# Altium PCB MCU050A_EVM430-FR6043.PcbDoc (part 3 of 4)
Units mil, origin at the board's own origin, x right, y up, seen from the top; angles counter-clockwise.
Board outline 6000 x 4000 mil, 4 copper layers (Top Layer, GND, PWR, Bottom Layer), stack 61.2 mil thick; 337 components, 255 nets, 1099 pads, 437 vias.
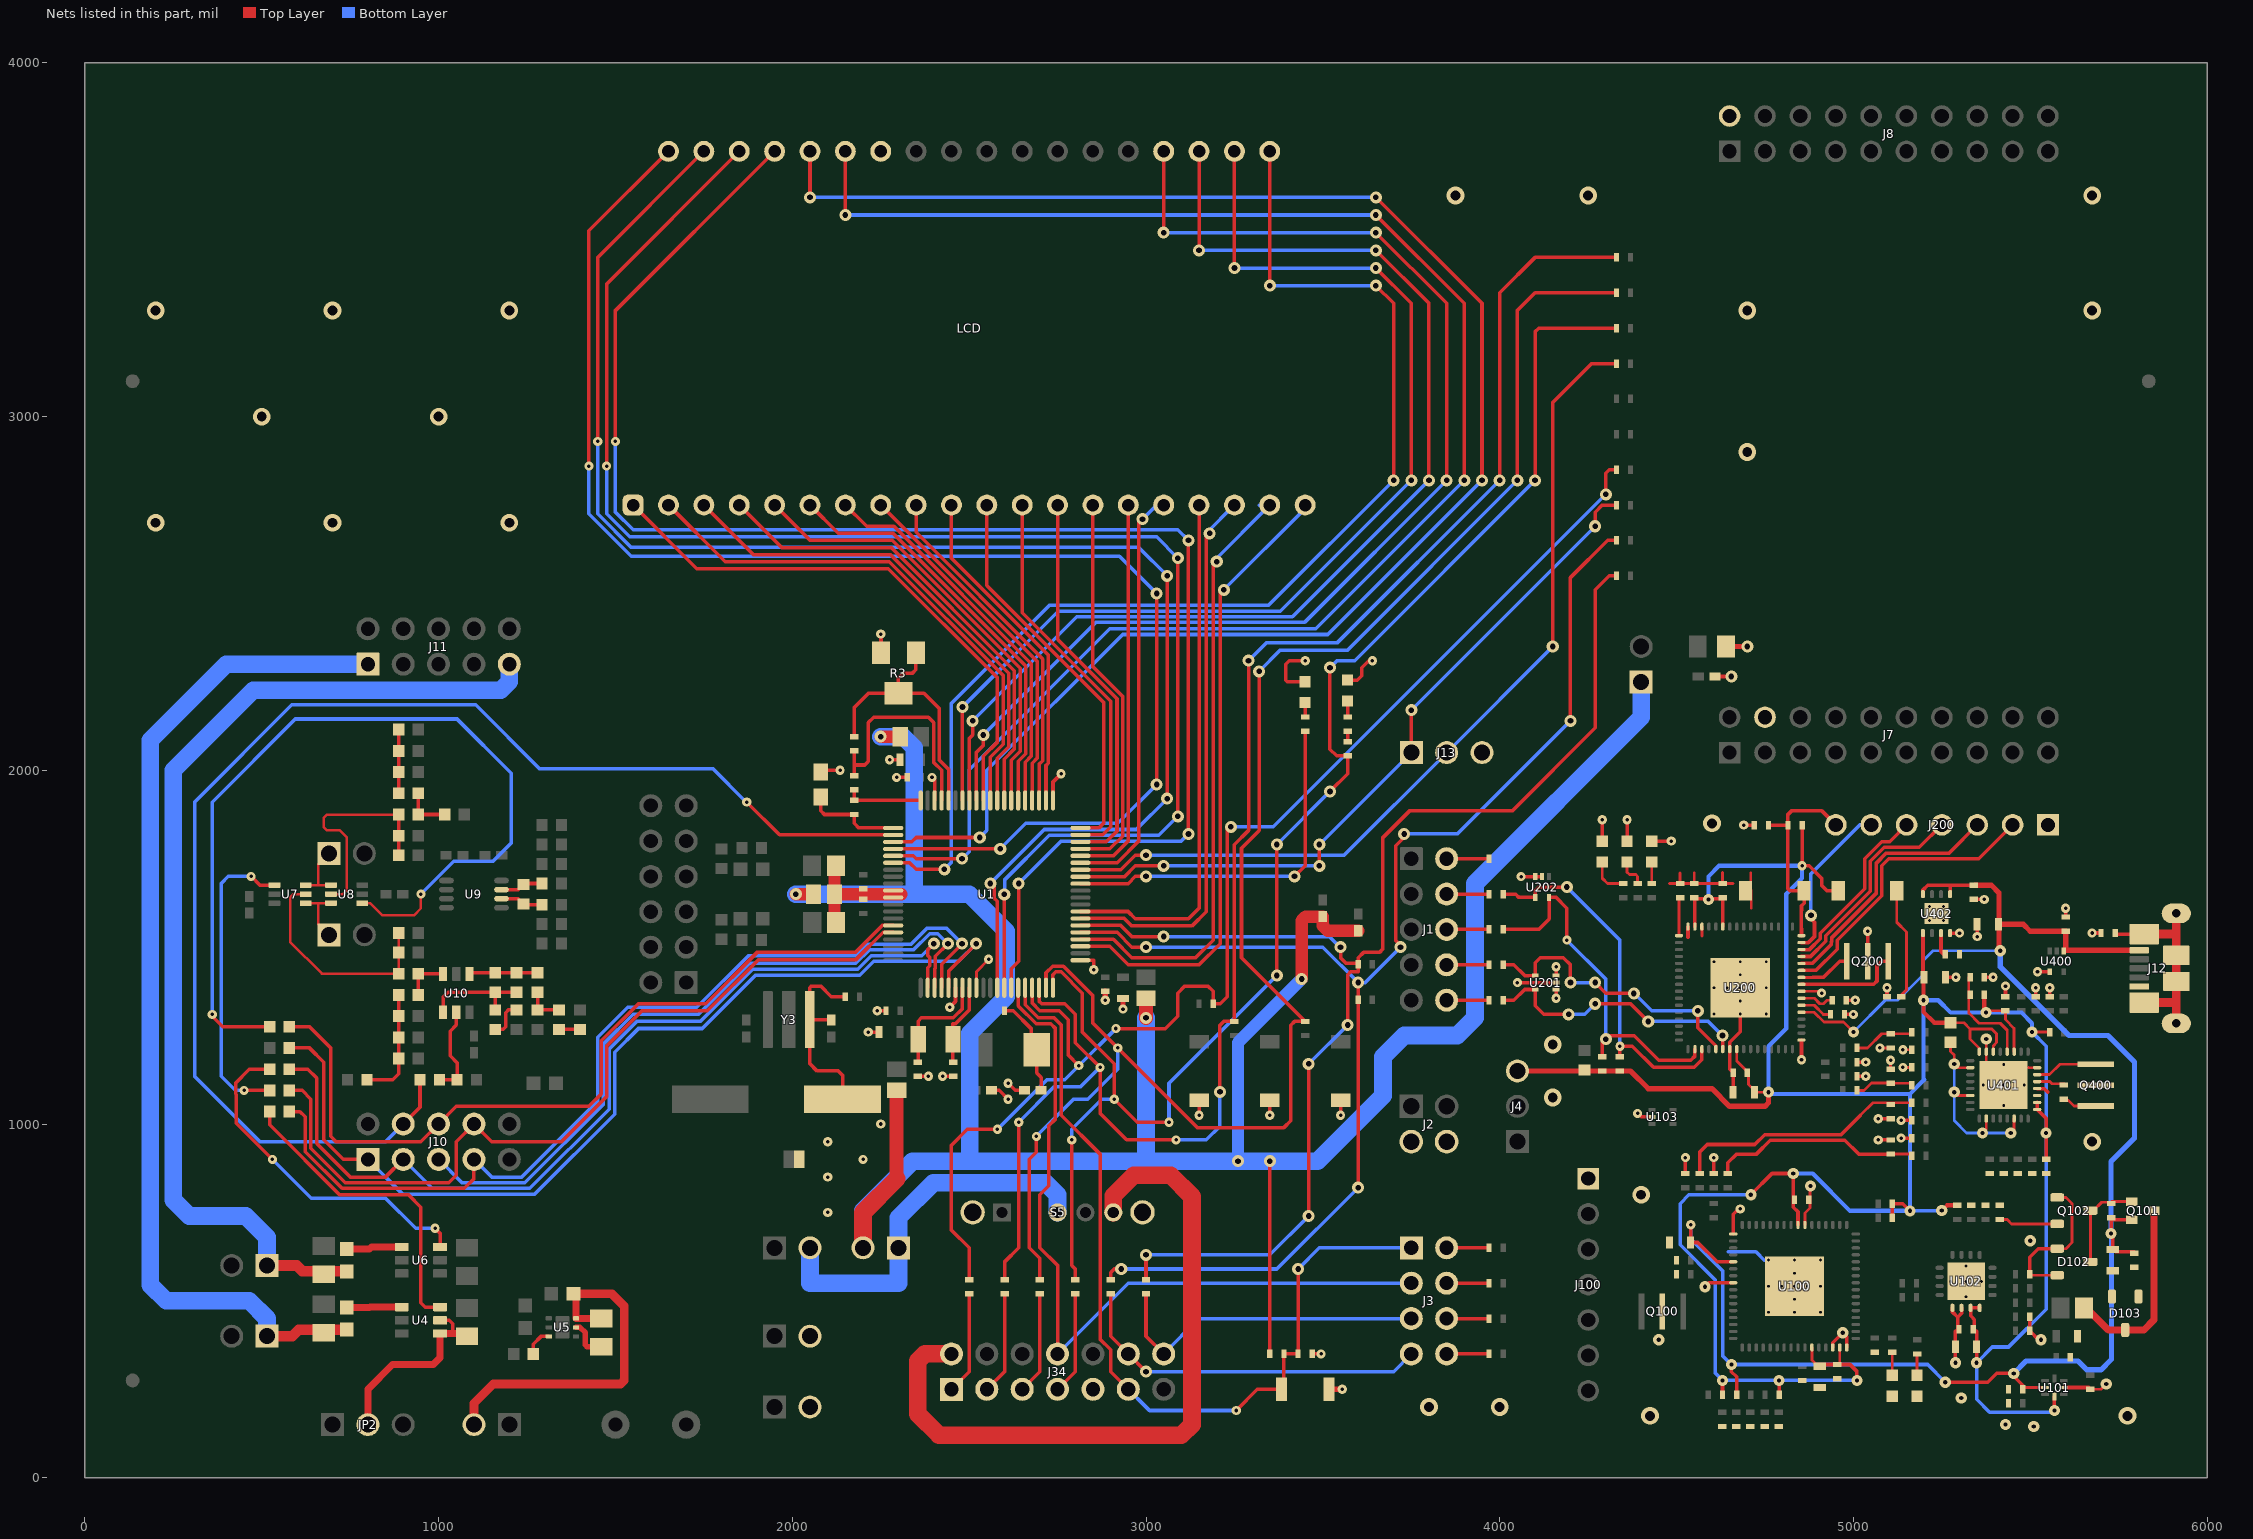
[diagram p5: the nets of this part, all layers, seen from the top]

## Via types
v1: diameter 26, hole 10, Top Layer to Bottom Layer, tented both sides, 173 vias
v2: diameter 34, hole 16, Top Layer to Bottom Layer, tented both sides, 142 vias
v3: diameter 31.5, hole 11.81, Top Layer to Bottom Layer, tented both sides, 56 vias
v4: diameter 19.68, hole 7.87, Top Layer to Bottom Layer, tented both sides, 35 vias
v5: diameter 50, hole 28, Top Layer to Bottom Layer, tented both sides, 23 vias
v6: diameter 19.68, hole 7.87, Top Layer to Bottom Layer, 7 vias
v7: diameter 34, hole 16, Top Layer to Bottom Layer, 1 vias

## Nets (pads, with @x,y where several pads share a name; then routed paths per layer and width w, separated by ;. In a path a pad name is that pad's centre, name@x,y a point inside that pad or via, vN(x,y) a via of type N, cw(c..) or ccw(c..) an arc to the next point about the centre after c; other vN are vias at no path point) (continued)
HID-BRIDGE_RST: C210.1 J200.7 R209.1 S201.2 U200.64 | length 599.8
  Top Layer w10: C210.1@4760,1845 R209.1@4815,1845 ; U200.64@4853.23,1532.68 4853.23,1551.65 4852,1552.88 4852,1602.83 4853.23,1604.05 4853.23,1617.06 4860.63,1624.46 S201.2@4860.63,1660 4820,1660 4815,1665 R209.1@4815,1845 ; J200.7@4950.31,1845.79 4911.1,1885 4825,1885 4815,1875 R209.1@4815,1845
HID-BRIDGE_RXD: R216.1 U200.38 U201.5 | length 776.8
  Top Layer w10: R216.1@4010,1350 4040.08,1350 4070.39,1380.31 U201.5@4100.47,1380.31 4100.47,1334.53 4125,1310 v2(4195,1310) ; v2(4270,1340) 4370,1340 v2(4420,1290) ; v2(4630,1250) 4630.79,1249.21 U200.38@4630.79,1211.77
  Bottom Layer w10: v2(4195,1310) 4240,1310 v2(4270,1340) ; v2(4420,1290) 4590,1290 v2(4630,1250)
HID-BRIDGE_SCL: R200.1 R213.1 U200.35 U202.4 | length 1045.6
  Top Layer w10: R213.1@4010,1650 4045,1650 4054.53,1640.47 U202.4@4100.31,1640.47 4100.31,1660.32 4110,1670 v2(4190,1670) ; R200.1@4340,1190 v1(4340,1220) 4375,1220 4435,1160 4550,1160 4571.73,1181.73 U200.35@4571.73,1211.77
  Bottom Layer w10: v2(4190,1670) 4340,1520 v1(4340,1220)
HID-BRIDGE_SDA: R208.1 R214.1 U200.34 U202.5 | length 1051.2
  Top Layer w10: R214.1@4010,1550 4110,1550 4139.69,1579.69 U202.5@4139.69,1640.47 4159.53,1640.47 4190,1610 v1(4190,1520) ; R208.1@4290,1190 4290,1230 v2(4300,1240) 4300,1250 4380,1250 4450,1180 4540,1180 4552.05,1192.05 U200.34@4552.05,1211.77
  Bottom Layer w10: v1(4190,1520) 4300,1410 v2(4300,1240)
HID-BRIDGE_TCK: J200.6 U200.63 | length 452.9
  Top Layer w10: U200.63@4853.23,1512.99 4872.98,1512.99 4890,1530 4890,1570 4880,1580 v2(4880,1590)
  Bottom Layer w10: v2(4880,1590) 4880,1707.17 5018.61,1845.79 J200.6@5050.31,1845.79
HID-BRIDGE_TDI: J200.4 U200.61 | length 610.1
  Top Layer w10: U200.61@4853.23,1473.61 4878.86,1473.61 4922,1516.75 4922,1532.25 5048,1658.25 5048,1743.25 5086.75,1782 5186.53,1782 J200.4@5250.31,1845.79
HID-BRIDGE_TDO: J200.3 U200.60 | length 719.5
  Top Layer w10: U200.60@4853.23,1453.91 4883.91,1453.91 4938,1508 4938,1515 4938.2,1515.2 4938.2,1525.82 5064,1651.63 5064,1736.63 5093.37,1766 5270.53,1766 J200.3@5350.31,1845.79
HID-BRIDGE_TEST: J200.2 U200.59 | length 832
  Top Layer w10: U200.59@4853.23,1434.22 4894.23,1434.22 4954.2,1494.2 4954.2,1519.2 5080,1645 5080,1730 5100,1750 5354.53,1750 J200.2@5450.31,1845.79
HID-BRIDGE_TMS: J200.5 U200.62 | length 502
  Top Layer w10: U200.62@4853.23,1493.3 4875.92,1493.3 4906,1523.37 4906,1538.88 5032,1664.88 5032,1749.88 5080.12,1798 5102.53,1798 J200.5@5150.31,1845.79
HID-BRIDGE_TXD: R215.1 U200.37 U201.4 | length 825.9
  Top Layer w10: R215.1@4010,1450 4040.08,1450 4070.39,1419.68 U201.4@4100.47,1419.68 4100.47,1455.47 4115,1470 4180,1470 4200,1450 v2(4200,1400) ; v2(4270,1400) 4300,1370 4378.37,1370 v2(4379.18,1369.18) ; v2(4560,1320) 4560,1272.51 4611.1,1221.41 U200.37@4611.1,1211.77
  Bottom Layer w10: v2(4200,1400) v2(4270,1400) ; v2(4379.18,1369.18) 4380,1370 4430,1320 v2(4560,1320)
HID-BRIDGE_V18: C207.1 U200.55 | length 97.3
  Top Layer w8: U200.55@4853.23,1355.47 4889.53,1355.47 4905,1340 4915,1340 4925,1350 C207.1@4940,1350
HID-BRIDGE_VCORE: C208.1 U200.17 | length 105
  Top Layer w8: U200.17@4506.77,1532.68 4506.77,1633.15 C208.1@4510,1636.38
HID-BRIDGE_VUSB: C206.1 U200.54 | length 92.4
  Top Layer w8: U200.54@4853.23,1335.78 4889.23,1335.78 4915,1310 C206.1@4935,1310
HID-BRIDGE_XT2IN: Q200.1 U200.57 | length 297.7
  Top Layer w10: U200.57@4853.23,1394.84 5057.33,1394.84 5066.75,1404.26 5066.75,1446.75 5080,1460 Q200.1@5099.06,1460
HID-BRIDGE_XT2OUT: Q200.3 U200.58 | length 146.5
  Top Layer w8: U200.58@4853.23,1414.53 4884.53,1414.53
  Top Layer w10: 4884.53,1414.53 4915.48,1414.53 4960.94,1460 Q200.3@4980.94,1460
HUB_DM1: R201.1 R412.2 R414.1 | length 160.7
  Top Layer w8: R201.1@5013.62,1215 5040,1215 5080,1255 R412.2@5105,1255 ; R412.2@5108.62,1255 R414.1@5161.38,1255
HUB_DM2: R101.1 R405.2 R415.1 | length 714.4
  Top Layer w8: 5020,1025 5055,1060 R415.1@5161.38,1060
  Top Layer w10: R101.1@4565,860 4565,920 4587,942 4721.6,942 4749.6,970 4965,970 5020,1025
HUB_DP1: R203.1 R411.2 R413.1 | length 153
  Top Layer w8: R203.1@5013.62,1095 5029.8,1095 5051.18,1116.38 R411.2@5105,1116.38 ; R411.2@5108.62,1115 R413.1@5161.38,1115
HUB_DP2: R100.1 R410.2 R416.1 | length 589
  Top Layer w8: R410.2@5105,915 R416.1@5161.38,915
  Top Layer w10: R100.1@4645,860 4645,890 4670,915 4726,915 4765,954 4976,954 5015,915 R410.2@5105,915
HUB_R\E\S\E\T\: C400.1 R404.1 U401.4 | length 290.6
  Top Layer w8: C400.1@5326.38,1415 5326.38,1313.62 5355,1285 5415,1285 5434.84,1265.16 U401.4@5434.84,1204.49
HUB_XTAL1: Q400.1 U401.30 | length 176.8
  Top Layer w8: U401.30@5519.49,1139.53 5554.53,1139.53 5584.06,1169.06 Q400.1@5684.06,1169.06
HUB_XTAL2: R406.2 U401.29 | length 78.1
  Top Layer w8: U401.29@5519.49,1119.84 5555.16,1119.84 5561.38,1113.62 R406.2@5595,1113.62
JTAG_RESET: C17.1 J3.1 J34.11 R2.1 S1.2 U1.16 | length 2492.9
  Top Layer w10: U1.16@2658.27,1385.24 2658.27,1336.73 2695,1300 2740,1300 2760,1280 2760,1025 2870,915 2870,391.49 2900,361.49 2900,300 J34.11@2950,250 ; v1(3255,190) 3315,250 S1.2@3383.07,250 3390,256.93 R2.1@3390,350 C17.1@3430,350 v2(3430,590)
  Bottom Layer w10: J34.11@2950,250 3000,200 3010,190 v1(3255,190) ; v2(3430,590) 3490,650 J3.1@3750,650
JTAG_RXD: J3.5 J34.14 R41.1 | length 932.1
  Top Layer w10: R41.1@3000,520 3000,400 J34.14@3050,350
  Bottom Layer w10: J34.14@3050,350 3150,450 J3.5@3750,450
JTAG_TCK: J34.7 R39.1 | length 290.7
  Top Layer w10: J34.7@2750,250 2800,300 R39.1@2800,520
JTAG_TDI: J34.3 R37.1 | length 290.7
  Top Layer w10: J34.3@2550,250 2600,300 R37.1@2600,520
JTAG_TDO: J34.1 R36.1 | length 290.7
  Top Layer w10: J34.1@2450,250 2500,300 R36.1@2500,520
JTAG_TEST: J3.3 J34.8 U1.15 | length 2225.1
  Top Layer w10: U1.15@2638.58,1385.24 2638.58,1333.79 2689.37,1283 2731,1283 2744,1270 2744,1014 2725,995 2725,825 2700,800 2700,650 2750,600 J34.8@2750,350
  Bottom Layer w10: J34.8@2750,350 2950,550 J3.3@3750,550
JTAG_TMS: J34.5 R38.1 | length 290.7
  Top Layer w10: J34.5@2650,250 2700,300 R38.1@2700,520
JTAG_TXD: J3.7 J34.12 R40.1 | length 1032.1
  Top Layer w10: R40.1@2900,520 2900,400 J34.12@2950,350 v2(3000,300)
  Bottom Layer w10: v2(3000,300) 3700,300 J3.7@3750,350
JTAG_VCC: J34.2 S5.4 | length 2029.2
  Top Layer w50: J34.2@2450,350 2375,350 2355,330 2355,180 2415,120 3100,120 3130,150 3130,795 3070,855 2965,855 2907.48,797.48 S5.4@2907.48,750
LCD_COM0-COM0: LCD.24 U1.52 | length 3414.4
  Top Layer w10: U1.52@2520.47,1914.76 2520.47,2050.47 2540,2070 v2(2540,2100) ; v2(3050,3520) LCD.24@3050,3750 ; v2(3650,3520) 3850,3320 v2(3850,2820)
  Bottom Layer w10: v2(2540,2100) 2858,2418 3448,2418 v2(3850,2820) ; v2(3050,3520) v2(3650,3520)
LCD_COM1-COM1: LCD.23 U1.53 | length 3292.8
  Top Layer w10: U1.53@2500.79,1914.76 2500.79,2090.79 2510,2100 v2(2510,2140) ; v2(3150,3470) LCD.23@3150,3750 ; v2(3650,3470) 3800,3320 v2(3800,2820)
  Bottom Layer w10: v2(2510,2140) 2804,2434 3414,2434 v2(3800,2820) ; v2(3150,3470) v2(3650,3470)
LCD_COM2-COM2: LCD.22 U1.54 | length 3170
  Top Layer w10: U1.54@2481.1,1914.76 v2(2481.1,2178.9) ; v2(3250,3420) LCD.22@3250,3750 ; v2(3650,3420) 3750,3320 v2(3750,2820)
  Bottom Layer w10: v2(2481.1,2178.9) 2752.2,2450 3380,2450 v2(3750,2820) ; v2(3250,3420) v2(3650,3420)
LCD_COM3-COM3: LCD.21 U1.66 | length 3392.4
  Top Layer w10: U1.66@2285.24,1738.58 2331.42,1738.58 2350,1720 v2(2430,1720) ; v2(3350,3370) LCD.21@3350,3750 ; v2(3650,3370) 3700,3320 v2(3700,2820)
  Bottom Layer w10: v2(2430,1720) 2450,1740 2450,2190 2726,2466 3346,2466 v2(3700,2820) ; v2(3350,3370) v2(3650,3370)
LCD_R03: R3.1 R3.2 R4.2 U1.56 | length 777.7
  Top Layer w10: R4.2@2175,2095 2175,2177.56 2215.35,2217.91 R3.2@2300,2217.91 ; R3.1@2349.21,2332.09 2349.21,2284.21 2340,2275 2315,2275 2300,2260 R3.2@2300,2217.91 ; U1.56@2441.73,1914.76 2441.73,2002.94 2416,2028.67 2416,2174.2 2372.28,2217.91 R3.2@2300,2217.91
LCD_R13_REF: R4.1 R5.1 U1.57 | length 650.9
  Top Layer w10: R5.1@2175,1985 2175,2015 ; R4.1@2175,2055 2175,2015 ; U1.57@2422.05,1914.76 2422.05,2000 2400,2022.05 2400,2135 2385,2150 2230,2150 2215,2135 2215,2025 2205,2015 2175,2015
LCD_R23: R5.2 R6.1 U1.60 | length 217.8
  Top Layer w10: R6.1@2175,1915 R5.2@2175,1945 ; R6.1@2175.24,1914.76 U1.60@2362.99,1914.76
LCD_R33_CAP: C18.1 R6.2 U1.61 | length 274.2
  Top Layer w10: C18.1@2080,1920 2080,1886 2091,1875 R6.2@2175,1875 2175,1850 2187.99,1837.01 U1.61@2285.24,1837.01
LCDS0-1: LCD.1 U1.51 | length 1595.6
  Top Layer w10: LCD.1@1550,2750 1730,2570 2271.61,2570 2580,2261.61 2580,2080 2540.16,2040.16 U1.51@2540.16,1914.76
LCDS1-2: LCD.2 U1.50 | length 1514
  Top Layer w10: LCD.2@1650,2750 1810,2590 2274.24,2590 2596,2268.24 2596,2073.37 2559.84,2037.22 U1.50@2559.84,1914.76
LCDS2-3: LCD.3 U1.49 | length 1432.4
  Top Layer w10: LCD.3@1750,2750 1890,2610 2276.86,2610 2612,2274.86 2612,2066.75 2579.53,2034.27 U1.49@2579.53,1914.76
LCDS3-4: LCD.4 U1.48 | length 1350.7
  Top Layer w10: LCD.4@1850,2750 1970.25,2629.75 2279.75,2629.75 2628,2281.49 2628,2060.12 2599.21,2031.33 U1.48@2599.21,1914.76
LCDS4-5: LCD.5 U1.47 | length 1269.1
  Top Layer w10: LCD.5@1950,2750 2050,2650 2282.12,2650 2644,2288.12 2644,2053.49 2618.9,2028.39 U1.47@2618.9,1914.76
LCDS5-6: LCD.6 U1.46 | length 1187.4
  Top Layer w10: LCD.6@2050,2750 2130,2670 2284.75,2670 2660,2294.75 2660,2046.86 2638.58,2025.45 U1.46@2638.58,1914.76
LCDS6-7: LCD.7 U1.45 | length 1105.8
  Top Layer w10: LCD.7@2150,2750 2210,2690 2287.37,2690 2676,2301.37 2676,2040.24 2658.27,2022.5 U1.45@2658.27,1914.76
LCDS7-8: LCD.8 U1.44 | length 1024.1
  Top Layer w10: LCD.8@2250,2750 2692,2308 2692,2033.61 2677.95,2019.56 U1.44@2677.95,1914.76
LCDS8-9: LCD.9 U1.43 | length 987.8
  Top Layer w10: LCD.9@2350,2750 2350,2672.63 2708,2314.63 2708,2026.98 2697.64,2016.62 U1.43@2697.64,1914.76
LCDS9-10: LCD.10 U1.42 | length 951.5
  Top Layer w10: LCD.10@2450,2750 2450,2600 2724,2326 2724,2020.35 2717.32,2013.68 U1.42@2717.32,1914.76
LCDS10-11: LCD.11 U1.40 | length 1107.3
  Top Layer w10: LCD.11@2550,2750 2550,2522.63 2880,2192.63 2880,1850 2867.01,1837.01 U1.40@2814.76,1837.01
LCDS11-12: LCD.12 U1.39 | length 1108.2
  Top Layer w10: LCD.12@2650,2750 2650,2445.25 2900,2195.25 2900,1840 2877.32,1817.32 U1.39@2814.76,1817.32
LCDS12-13: LCD.13 U1.38 | length 1107.4
  Top Layer w10: LCD.13@2750,2750 2750,2370 2918,2202 2918,1828 2887.64,1797.64 U1.38@2814.76,1797.64
LCDS13-14: LCD.14 U1.37 | length 1105
  Top Layer w10: U1.37@2814.76,1777.95 2897.95,1777.95 2934,1814 2934,2208.63 2850,2292.63 LCD.14@2850,2750
LCDS14-15: LCD.15 U1.36 | length 1096.7
  Top Layer w10: U1.36@2814.76,1758.27 2908.27,1758.27 2950,1800 2950,2730 LCD.15@2960,2740
LCDS15-16: LCD.16 U1.35 | length 1187.2
  Top Layer w10: U1.35@2814.76,1738.58 2918.58,1738.58 2980,1800 2980,2710 v2(2990,2710)
  Bottom Layer w10: v2(2990,2710) 3030,2750 LCD.16@3050,2750
LCDS18-17: LCD.17 U1.28 | length 1496.3
  Top Layer w10: U1.28@2814.76,1600.79 2949.21,1600.79 2970,1580 3120,1580 3150,1610 LCD.17@3150,2750
LCDS19-18: LCD.18 U1.27 | length 1573.7
  Top Layer w10: U1.27@2814.76,1581.1 2938.9,1581.1 2960,1560 3130,1560 3170,1600 v2@3170,2670
  Bottom Layer w10: v2(3180,2670) 3170,2670 LCD.18@3250,2750
LCDS20-19: LCD.19 U1.24 | length 1757.9
  Top Layer w10: U1.24@2814.76,1522.05 2907.95,1522.05 2960,1470 3140,1470 3190,1520 3190,2580 v2(3200,2590)
  Bottom Layer w10: v2(3200,2590) 3190,2590 LCD.19@3350,2750 3320,2750
LCDS21-20: LCD.20 U1.23 | length 1787
  Top Layer w10: U1.23@2814.76,1502.36 2897.64,1502.36 2950,1450 3150,1450 3210,1510 3210,2510 v2(3220,2510)
  Bottom Layer w10: v2(3220,2510) 3450,2740 LCD.20@3450,2750
LCDS22-35: LCD.35 U1.14 | length 4531
  Top Layer w10: v1(1500,2930) 1500,3300 LCD.35@1950,3750 ; U1.14@2618.9,1385.24 2618.9,1438.9 2640,1460 v2(2640,1680) ; v2(3120,1820) v2(3120,2650)
  Bottom Layer w10: v1(1500,2930) 1500,2730 1550,2680 3090,2680 v2(3120,2650) ; v2(2640,1680) 2760,1800 3100,1800 v2(3120,1820)
LCDS23-36: LCD.36 U1.13 | length 4446.8
  Top Layer w10: v1(1475,2860) 1475,3375 LCD.36@1850,3750 ; U1.13@2599.21,1385.24 v2(2599.21,1649.21) ; v2(3090,1870) v2(3090,2600)
  Bottom Layer w10: v1(1475,2860) 1475,2725 1540,2660 3030,2660 v2(3090,2600) ; v2(2599.21,1649.21) 2600,1650 2600,1690 2726,1816 3036,1816 v2(3090,1870)
LCDS24-37: LCD.37 U1.12 | length 4364
  Top Layer w10: v1(1450,2930) 1450,3450 LCD.37@1750,3750 ; v2(2560,1680) 2571.21,1668.79 2571.21,1637.61 2576.31,1632.51 ; 2576.31,1632.47 2577.62,1631.16 2577.62,1630.95 2578.8,1629.78 2578.8,1440.26 2579.53,1439.53 U1.12@2579.53,1385.24 ; v2(3060,1920) v2(3060,2550)
  Bottom Layer w10: v1(1450,2930) 1450,2725 1545,2630 2980,2630 v2(3060,2550) ; v2(2560,1680) 2712.68,1832.68 2972.68,1832.68 v2(3060,1920)
LCDS25-38: LCD.38 U1.64 | length 4176.6
  Top Layer w10: v1(1425,2860) 1425,3525 LCD.38@1650,3750 ; U1.64@2285.24,1777.95 2491.6,1778 2491.65,1777.95 v2(2587.95,1777.95) ; v2(3030,1960) v2(3030,2500)
  Bottom Layer w10: v1(1425,2860) 1425,2725 1545,2605 2925,2605 v2(3030,2500) ; v2(2587.95,1777.95) 2660,1850 2920,1850 v2(3030,1960)
LCDS27-33: LCD.33 U1.65 | length 4730.9
  Top Layer w10: v2(2150,3570) LCD.33@2150,3750 ; U1.65@2285.24,1758.27 2341.73,1758.27 2350,1750 v2(2480,1750) ; v2(3650,3570) 3900,3320 v2(3900,2820)
  Bottom Layer w10: v2(2150,3570) v2(3650,3570) ; v2(2480,1750) 2500,1770 2500,2002 2898,2400 3480,2400 v2(3900,2820)
LCDS28-34: LCD.34 U1.63 | length 4842.1
  Top Layer w10: v2(2050,3620) LCD.34@2050,3750 ; U1.63@2285.24,1797.64 2337.64,1797.64 2350,1810 v2(2530,1810) ; v2(3650,3620) 3950,3320 v2(3950,2820)
  Bottom Layer w10: v2(2050,3620) v2(3650,3620) ; v2(2530,1810) 2550,1830 2550,2000 2934,2384 3514,2384 v2(3950,2820)
LED1: R7.1 R52.1 | length 30
  Top Layer w10: R52.1@3570,2080.83 R7.1@3570,2110.83
LED2: R8.1 U1.32 | length 1037
  Top Layer w10: U1.32@2814.76,1679.53 2949.53,1679.53 2970,1700 v2(3000,1700) ; v2(3420,1700) 3450,1730 R8.1@3450,2110.83
  Bottom Layer w10: v2(3000,1700) v2(3420,1700)
LFXIN: C13.1 U1.7 Y2.1 | length 315.2
  Top Layer w10: C13.1@2355,1175 2355.79,1175.79 Y2.1@2355.79,1240 2355.79,1290.79 2365,1300 2455,1300 2481.1,1326.1 U1.7@2481.1,1385.24
LFXOUT: C14.2 U1.8 Y2.2 | length 233.7
  Top Layer w10: C14.2@2455,1175 2454.21,1175.79 Y2.2@2454.21,1240 2454.21,1283.21 2455,1284 2461.63,1284 2500.79,1323.16 U1.8@2500.79,1385.24
MCU_VCC: J30.1 J32.2 L1.2 L2.1 L3.2 L4.2 R2.2 R11.2 R12.2 | length 7670.6
  Top Layer w10: R2.2@3350,350 v2(3350,895)
  Top Layer w35: v2(2010,1650) L2.1@2060.16,1650 ; v2(2250,2095) L4.2@2305.47,2095 ; v2(3440,1410) 3440,1575 3451.38,1586.38 R11.2@3500,1586.38 3500,1560 3513.62,1546.38 R12.2@3600,1546.38
  Top Layer w40: 2295,845 L1.2@2295,1095.47 ; v7(3000,1300) L3.2@3000,1355.47
  Top Layer w50: J32.2@2200,650 2200,750 2295,845
  Bottom Layer w35: v2(3260,895) 3260,1230 v2(3440,1410)
  Bottom Layer w50: v2(2010,1650) 2345,1650 ; J32.2@2200,650 2200,755 2340,895 2500,895 ; v2(2250,2095) 2313.5,2095 2345,2063.5 2345,1650 ; v7(3000,1300) 3000,895 ; J30.1@4400,2250 4400,2150 3930,1680 3930,1300 3880,1250 3730,1250 3670,1190 3670,1080 3485,895 v2(3350,895) v2(3260,895) 3000,895 ; 2345,1650 2500,1650 2605,1545 2605,1360 2502,1257 2502,897 2500,895 ; 2500,895 3000,895
MTIF_OUT_IN: J13.1 R28.1 U1.33 | length 2079.4
  Top Layer w10: U1.33@2814.76,1699.21 2939.21,1699.21 2970,1730 v2(3050,1730) ; v2(3490,1730) v2(3490,1790) ; J13.1@3750,2050 v2(3750,2170) ; v2(4270,2690) 4270,2730 4290,2750 R28.1@4330,2750
  Bottom Layer w10: v2(3050,1730) v2(3490,1730) ; v2(3490,1790) J13.1@3750,2050 ; v2(3750,2170) v2(4270,2690)
MTIF_PIN_EN: J13.2 R35.1 U1.34 | length 2512.2
  Top Layer w10: U1.34@2814.76,1718.9 2928.9,1718.9 2970,1760 v2(3000,1760) ; v2(4150,2350) 4150,3040 4260,3150 R35.1@4330,3150
  Bottom Layer w10: v2(3000,1760) 3560,1760 J13.2@3850,2050 v2(4150,2350)
NetC11_1: C11.1 R1.1 Y3.1 Y4.2 | length 565.9
  Top Layer w10: C11.1@2110,1293.62 2108.62,1295 Y3.1@2049.06,1295 ; Y4.2@2142.01,1070 2142.01,1137.99 2130,1150 2070,1150 2049.06,1170.94 Y3.1@2049.06,1295 ; R1.1@2150,1360 2110,1360 2080,1390 2053.5,1390 2049.06,1385.55 Y3.1@2049.06,1295
NetC15_1: C15.1 R9.1 Y1.2 | length 282.6
  Top Layer w10: R9.1@2600,1320 2625,1320 2675,1270 2675,1225.71 Y1.2@2690.71,1210 2690.71,1144.29 2703.62,1131.38 C15.1@2703.62,1095
NetC25_1: C25.1 JP2.2 U4.4 U4.5 | length 558.5
  Top Layer w10: U4.5@999.13,445 1029.99,445 1039.99,435 1039.99,408.48 1039.11,407.6
  Top Layer w20: JP2.2@800,150 800,249.99 870,320 985,320 1004.13,339.13 U4.4@1004.13,407.6 1039.11,407.6 1079.09,407.6 C25.1@1079.99,408.5
NetC28_1: C28.1 JP1.2 L6.2 U5.6 | length 1021.5
  Top Layer w20: C28.1@1381.49,520 1388.38,513.11 U5.6@1388.38,450.59 L6.2@1450.59,450.59
  Top Layer w25: JP1.2@1100,150 1100,210 1155,265 1515,265 1525,275 1525,485 1490,520 C28.1@1381.49,520 ; L6.2@1455,455 L6.2@1460,450
NetC35_2: C35.2 R42.1 R44.2 R45.2 | length 180
  Top Layer w10: R42.1@887.44,1935 C35.2@887.44,1995 R45.2@887.44,2055 R44.2@887.44,2115
NetC36_2: C36.2 R42.2 R43.1 | length 134.9
  Top Layer w10: R42.2@942.56,1935 C36.2@942.56,1875 R43.1@1017.44,1875
NetC39_1: C39.1 R61.2 R63.1 U10.1 | length 189.2
  Top Layer w10: U10.1@1090.83,1427.56 R61.2@1160,1427.56 C39.1@1220,1427.56 R63.1@1280,1427.56
NetC39_2: C39.2 R60.2 R61.1 U10.4 | length 305.2
  Top Layer w10: U10.4@1012.6,1315.87 1012.6,1357.6 1027.44,1372.44 R61.1@1160,1372.44 ; R60.2@1160,1322.56 R61.1@1160,1372.44 ; C39.2@1220,1372.44 R61.1@1160,1372.44
NetC40_2: C40.2 R60.1 | length 106.3
  Top Layer w10: R60.1@1160,1267.44 1182.44,1267.44 1190,1275 1190,1315 1197.56,1322.56 C40.2@1220,1322.56
NetC42_2: C42.2 R64.1 | length 60
  Top Layer w10: R64.1@1340,1267.44 C42.2@1400,1267.44
NetC43_2: C43.2 R66.2 U10.3 | length 129.2
  Top Layer w10: R66.2@942.56,1365 C43.2@942.56,1425 U10.3@1011.73,1425
NetC44_1: C44.1 R63.2 R64.2 | length 109.9
  Top Layer w10: R63.2@1280,1372.44 C44.1@1280,1322.56 R64.2@1340,1322.56
NetC45_2: C45.2 R65.1 R66.1 R67.2 R74.1 | length 319.7
  Top Layer w10: R74.1@797.56,1125 870,1125 887.44,1142.44 R65.1@887.44,1185 R67.2@887.44,1245 C45.2@887.44,1305 R66.1@887.44,1365
NetC412_1: C412.1 U402.3 | length 63.4
  Top Layer w12: U402.3@5247.8,1539.88 5247.8,1488.58 C412.1@5256.38,1480
NetD1_1: D1.1 R8.2 | length 40.5
  Top Layer w10: R8.2@3450,2150.83 D1.1@3450,2191.3
NetD2_1: D2.1 R7.2 | length 45.1
  Top Layer w10: R7.2@3570,2150.83 D2.1@3570,2195.89
NetD102_1: D102.1 D102.2 Q102.1 R122.1 | length 420.3
  Top Layer w8: R122.1@5502.13,575 5504.53,572.6 D102.2@5576.26,572.6 ; D102.1@5576.26,647.4 5600.91,647.4 5618.5,665 5618.5,775 5601.1,792.4 Q102.1@5576.26,792.4
  Top Layer w10: R122.1@5498.5,575 5498.5,623.5 5522.4,647.4 D102.1@5576.26,647.4
NetD102_3: D102.3 Q101.1 Q102.3 R120.2 | length 271.9
  Top Layer w8: D102.3@5670.75,610 Q102.3@5670.75,755 5678.5,755 5702.13,778.62 5728.5,778.62 5730.47,780.59 Q101.1@5787.01,780.59
NetD103_3: D103.3 L101.1 Q101.3 | length 537.7
  Top Layer w20: L101.1@5658.5,480 5720.75,417.76 D103.3@5768.5,417.76 5821.26,417.76 5850,446.5 Q101.3@5850,755
NetFB1_1: FB1.1 U4.1 | length 155
  Top Layer w20: FB1.1@740,481.49 805,481.49 ; 805.9,482.4 U4.1@895.86,482.4
NetFB2_1: FB2.1 U6.1 | length 150
  Top Layer w20: FB2.1@740,646.49 805,646.49 ; 810.9,652.4 U6.1@895.86,652.4
NetJ1_2: J1.2 R212.2 | length 120
  Top Layer w10: J1.2@3850,1750 R212.2@3970,1750
NetJ1_4: J1.4 R213.2 | length 120
  Top Layer w10: J1.4@3850,1650 R213.2@3970,1650
NetJ1_6: J1.6 R214.2 | length 120
  Top Layer w10: J1.6@3850,1550 R214.2@3970,1550
NetJ1_8: J1.8 R215.2 | length 120
  Top Layer w10: J1.8@3850,1450 R215.2@3970,1450
NetJ1_10: J1.10 R216.2 | length 120
  Top Layer w10: J1.10@3850,1350 R216.2@3970,1350
NetJ3_2: J3.2 R125.2 | length 120
  Top Layer w10: J3.2@3850,650 R125.2@3970,650
NetJ3_4: J3.4 R126.2 | length 120
  Top Layer w10: J3.4@3850,550 R126.2@3970,550
NetJ3_6: J3.6 R127.2 | length 120
  Top Layer w10: J3.6@3850,450 R127.2@3970,450
NetJ3_8: J3.8 R128.2 | length 120
  Top Layer w10: J3.8@3850,350 R128.2@3970,350
NetJ5_1: J5.1 U7.6 U8.4 | length 173.3
  Top Layer w7: U7.6@624.29,1675.59 660,1675.59 ; J5.1@690,1765 660,1735 660,1675.59 ; U8.4@695.71,1675.59 660,1675.59
NetJ6_1: J6.1 U7.4 U8.6 | length 173.3
  Top Layer w7: U7.4@624.29,1624.41 660,1624.41 ; J6.1@690,1535 660,1565 660,1624.41 ; U8.6@695.71,1624.41 660,1624.41
NetL6_1: L6.1 U5.5 | length 109.9
  Top Layer w15: U5.5@1388.38,425 1400,425 1415,409.99 1415,375 1420,370 L6.1@1455,370
NetLED101_1: LED101.1 R104.1 | length 65.5
  Top Layer w8: LED101.1@5110,289.53 R104.1@5110,355
NetLED102_1: LED102.1 R105.1 | length 60.5
  Top Layer w8: LED102.1@5180,289.53 R105.1@5180,350
NetLED201_1: LED201.1 R202.1 | length 111.7
  Top Layer w8: LED201.1@4290,1740.47 4290,1695 4305,1680 R202.1@4350,1680
NetLED202_1: LED202.1 R204.1 | length 83.6
  Top Layer w8: LED202.1@4360,1740.47 4360,1711.65 4366.65,1705 4385,1705 4390,1700 4390,1681.65 R204.1@4390,1680
NetLED203_1: LED203.1 R205.1 | length 56.9
  Top Layer w8: R205.1@4430,1683.62 LED203.1@4430,1740.47
NetQ102_2: Q102.2 R124.1 | length 167.9
  Top Layer w8: R124.1@5413.5,730 5435,730 5447.4,717.6 Q102.2@5576.26,717.6
NetQ400_3: Q400.3 R406.1 | length 96.4
  Top Layer w8: R406.1@5595,1066.38 5608.62,1066.38 5624.06,1050.95 Q400.3@5685,1050.95
NetR23_2: R23.2 U5.3 | length 80.7
  Top Layer w10: R23.2@1267.56,350 1267.56,377.56 1289.41,399.41 U5.3@1311.61,399.41
NetR46_2: R46.2 R81.2 U9.7 | length 121.8
  Top Layer w10: U9.7@1177.76,1662.8 1225.24,1662.8 R81.2@1240,1677.56 1242.44,1680 R46.2@1292.44,1680
NetR48_2: R48.2 R81.1 U9.6 | length 121.8
  Top Layer w10: U9.6@1177.76,1637.2 1225.24,1637.2 R81.1@1240,1622.44 1242.44,1620 R48.2@1292.44,1620
NetR62_2: R62.2 R68.1 U10.5 | length 256.3
  Top Layer w10: R68.1@1002.56,1125 R62.2@1052.44,1125 1052.44,1172.56 1032.44,1192.56 1032.44,1262.44 1050,1280 U10.5@1050,1315.87
NetR211_2: R211.2 S202.1 | length 321.8
  Top Layer w8: S202.1@5122.68,1660 5122.68,1570.39 5150,1543.07 5150,1379.39 R211.2@5128.9,1358.3
NetR418_1: R418.1 U401.10 U401.14 U401.18 U401.22 | length 588.6
  Top Layer w8: R418.1@5275,1231.06 5275,1205 5285,1195 v3(5285,1170) 5295.79,1159.21 U401.10@5330.51,1159.21 ; v3(5285,1090) 5294.53,1080.47 U401.14@5330.51,1080.47 ; v3(5365,975) 5375.79,985.79 U401.18@5375.79,1015.51 ; v3(5445,975) 5454.53,984.53 U401.22@5454.53,1015.51
  Bottom Layer w8: v3(5285,1170) v3(5285,1090) 5285,1010 5320,975 v3(5365,975) v3(5445,975)
PVCC: C4.2 C5.1 C9.2 C10.1 L2.2 U1.70 U1.71 | length 329.1
  Top Layer w35: C10.1@2119.21,1570 L2.2@2119.21,1650 C9.2@2119.21,1730 ; L2.2@2139.53,1650 2308.66,1650
PWRSRC_RX: C32.1 FB2.2 J11.9 JP5.1 | length 2938.9
  Top Layer w30: JP5.1@515,600 598.5,600 615,583.5 675,583.5 FB2.2@740,583.5
  Bottom Layer w50: JP5.1@515,600 515,680 455,740 295,740 250,785 250,2000 476,2226 1176,2226 1200,2250 J11.9@1200,2300
PWRSRC_TX: C27.1 FB1.2 J11.1 JP4.1 | length 2905.3
  Top Layer w30: JP4.1@521.5,393.5 JP4.1@515,400 586.5,400 605,418.5 675,418.5 FB1.2@740,418.5
  Bottom Layer w50: JP4.1@515,400 515,450 465,500 230,500 185,545 185,2085 400,2300 J11.1@800,2300
RX_MUX: R69.2 U7.1 | length 868.1
  Top Layer w10: v1(450,1095) R69.2@522.44,1095 ; v1(470,1700) 494.41,1675.59 U7.1@535.71,1675.59
  Bottom Layer w10: v1(450,1095) 425,1095 385,1135 385,1680 405,1700 v1(470,1700)
RX_PWRSW: R72.1 U6.6 | length 970.9
  Top Layer w10: R72.1@522.44,1155 465,1155 426,1116 426,1085.06 428.03,1083.03 428.03,1001.97 v1(530,900) ; v1(990,705) 1004.13,690.86 U6.6@1004.13,652.4
  Bottom Layer w10: v1(530,900) 640,790 850,790 935,705 v1(990,705)
RxEn: J10.4 R68.2 U1.62 | length 3848.4
  Top Layer w10: J10.4@900,1000 947.44,1047.44 R68.2@947.44,1125 ; v1(1871.25,1910) 1963.93,1817.32 U1.62@2285.24,1817.32
  Bottom Layer w10: J10.4@900,1000 850,950 495,950 310,1135 310,1910 585,2185 1105,2185 1285,2005 1775,2005 1870,1910 v1(1871.25,1910)
RxPwr: J10.3 R72.2 U1.2 | length 2634.1
  Top Layer w10: R72.2@577.56,1155 630,1155 655,1130 655,945 750,850 850,850 J10.3@900,900 ; U1.2@2382.68,1385.24 2382.68,1441.43 2388.5,1447.25 2388.5,1470.86 2383.5,1475.86 2383.5,1493.5 v2(2400,1510)
  Bottom Layer w10: J10.3@900,900 982,818 1258,818 1482,1042 1482,1212 1560,1290 1740,1290 1888,1438 2185.37,1438 2223.37,1476 2366,1476 v2(2400,1510)
RxSel1: J10.6 R70.2 U1.75 | length 2329.9
  Top Layer w10: R70.2@577.56,1275 635,1275 695,1215 695,965 710,950 950,950 J10.6@1000,1000 1050,1050 1425,1050 1460,1085 1460,1235 1565,1340 1755,1340 1900,1485 2177.63,1485 2254.04,1561.42 U1.75@2285.24,1561.42
RxSel2: J10.8 R69.1 U1.76 | length 2371
  Top Layer w10: R69.1@577.56,1095 614,1095 639,1070 639,931 736,834 1029,834 1050,855 1050,950 J10.8@1100,1000 1150,950 1347.63,950 1476,1078.37 1476,1221 1575,1320 1760,1320 1905,1465 2180.25,1465 2256.99,1541.73 U1.76@2285.24,1541.73
SIGNAL_RX: C43.1 R49.2 R59.2 U7.5 | length 633.2
  Top Layer w7: U7.5@624.29,1650 590,1650 580,1640 580,1515 670,1425 C43.1@887.44,1425 R59.2@887.44,1485 R49.2@887.44,1540
SIGNAL_TX: C36.1 R47.2 R51.2 U8.5 | length 633
  Top Layer w7: U8.5@695.71,1650 730,1650 740,1660 740,1811 721,1830 685,1830 675,1840 675,1865 685,1875 C36.1@887.44,1875
  Top Layer w10: R47.2@887.44,1760 R51.2@887.44,1815 C36.1@887.44,1875
TARGET_GND: C1.2 C2.1 C3.2 C6.2 C7.1 C8.1 C13.2 C14.1 C15.2 C16.2 C17.2 C18.2 C23.2 C24.2 C100.2 C101.2 C102.2 C103.2 C104.2 C105.2 C106.2 C107.2 C108.2 C109.2 C110.2 C111.2 C112.2 C113.2 C114.2 C115.2 C116.2 C117.2 C118.2 C119.2 C120.2 C121.2 C200.2 C201.2 C202.2 C203.2 C204.2 C205.2 C206.2 C207.2 C208.2 C210.2 C400.2 C401.2 C402.2 C403.2 C404.2 C405.2 C406.2 C407.2 C408.2 C409.2 C410.2 C411.2 C412.2 C413.2 D1.2 D2.2 D103.1 D103.2 J2.3 J2.4 J7.4 J8.2 J12.5 J13.3 J31.2 J33.2 J34.9 J100.1 J200.1 LCD.32 LED101.2 LED102.2 LED201.2 LED202.2 LED203.2 NT1.2 Q100.2 Q200.2 Q400.2 R3.3 R107.1 R109.1 R117.1 R119.1 R121.1 R123.1 R124.2 R210.1 R400.2 R401.2 R402.2 R403.2 R405.1 R410.1 R411.1 R412.1 RUSB.1 S1.1 S2.1 S3.1 S4.1 S5.S1 S5.S2 S201.1 U1.6 U1.9 U1.21 U1.41 U1.58 U100.14 U100.16 U100.39 U100.49 U100.56 U100.65 U101.6 U102.13 U102.14 U102.17 U103.2 U200.14 U200.16 U200.39 U200.49 U200.56 U200.65 U201.1 U201.2 U201.3 U202.2 U202.3 U400.4 U401.7 U401.27 U401.28 U401.31 U401.33 U402.4 U402.9 | length 5107.9
  Top Layer w8: U1.9@2520.47,1385.24 2520.47,1430.47 2555,1465 2555,1465.35 v1(2554.8,1465.55) ; 4480,1680 4660,1680 ; C208.2@4510,1680 4510,1710 ; C204.2@4550,1680 4550,1710 ; 4571.73,1531.73 U200.14@4571.73,1558.23 ; C202.2@4630,1680 4630,1711.04 ; S201.1@4710,1660 4710,1710 ; 4711.02,1611.02 S201.1@4711.02,1660 ; U200.56@4853.23,1375.16 4909.85,1375.16 4910,1375 v1(4910,1370) ; U100.39@4863.03,714.62 4863.03,748.03 4877.13,762.13 4877.13,823.62 v3(4878.5,825) ; v1(5075,1215) R412.1@5105,1215 ; R411.1@5105,1155 v1(5105,1180) ; v1(5140,1160) C406.2@5165,1160 ; v1(5140,1210) C407.2@5165,1210 ; v3@5375.79,1244.21 v3(5375.79,1240) U401.7@5375.79,1204.49 5375.79,1159.21 v4(5425,1110) ; 5495,1160 5495.79,1159.21 U401.31@5519.49,1159.21 ; R121.1@5670,250 5700,250 v3(5715,265)
  Top Layer w10: C18.2@2080,2000 v1(2135,2000) ; v1(2215,1260) C6.2@2245,1260 ; v1(2240,1320) C1.2@2265,1320 ; v1(2250,2385) 2250.79,2384.21 R3.3@2250.79,2332.09 ; v1(2275,2030) C8.1@2305,2030 ; v1(2295,1980) C3.2@2325,1980 ; C13.2@2355,1135 v1(2385,1135) ; v1(2395,1980) 2402.36,1972.64 U1.58@2402.36,1914.76 ; v1(2425,1135) C14.1@2455,1135 ; v1(2445,1330) 2461.42,1346.42 U1.6@2461.42,1385.24 ; C16.2@2563.62,1095 2585,1095 v1(2610,1070) ; v1(2610,1115) 2630,1095 C15.2@2656.38,1095 ; U1.21@2814.76,1462.99 2852.01,1462.99 v1(2852.01,1436.14) ; v1(3150.01,1025.01) S2.1@3150.01,1067.32 ; v1(3350.01,1025.01) S4.1@3350.01,1067.32 ; D1.2@3450,2250.36 3399.64,2250.36 3395,2255 3395,2300 3405,2310 v1(3450,2310) ; C17.2@3470,350 v1(3495,350) ; v1(3550.01,1024.99) S3.1@3550.01,1067.32 ; D2.2@3570,2254.94 3597.5,2254.94 3610,2267.44 3610,2290 3630,2310 v1(3640,2310) ; v1(4050,1400) U201.2@4159.53,1400 U201.2@4160,1400.47 ; v1(4060.47,1699.53) U202.3@4100.31,1699.53 U202.2@4120,1699.53 ; v1(4159.53,1355.47) U201.1@4159.53,1380.31 ; U201.3@4159.53,1419.68 v1(4159.53,1444.53) ; LED201.2@4290,1799.53 v1(4290,1860) ; LED202.2@4360,1799.53 v1(4360,1860) ; v1(4390,1030) 4400,1020 U103.2@4430.47,1020 ; LED203.2@4430,1799.53 4484.53,1799.53 v1(4485,1800) ; C101.2@4525,860 v1(4525,905) ; 4532.36,1527.64 U200.16@4532.36,1558.23 ; v3(4580,540) 4591.24,551.24 U100.56@4660.28,551.24 ; C100.2@4605,860 v1(4605,905) ; C205.2@4660,1090 C203.2@4660,1145 4650.47,1154.53 U200.39@4650.47,1211.77 4650.47,1230.87 4680,1260.4 v4(4680,1311.18) v4(4680,1348.09) ; U100.49@4660.28,689.07 4660.28,744.72 4675.55,760 v1(4680,760) ; v1(4690,1845) C210.2@4720,1845 ; v1(4853.23,1181.77) U200.49@4853.23,1237.32 ; U100.14@4941.77,368.17 4941.77,381.77 v3(4970,410) 4981.14,398.86 U100.16@4981.14,368.17 ; C206.2@4975,1310 v1(5000,1310) v1@5005,1310 ; C207.2@4980,1350 v1(5005,1350) ; C201.2@5010,1135 v1(5035,1135) ; C200.2@5010,1175 v1(5035,1175) ; Q200.2@5040,1460 v1(5040,1545) ; v1(5070,955) R410.1@5105,955 ; v1(5070,1015) R405.1@5105,1015 ; R210.1@5095,1360 v1(5095,1385) ; v1(5135,960) C405.2@5165,960 ; v1(5135,1010) C401.2@5165,1010 ; C413.2@5260,1415 v1(5290,1415) ; U402.4@5273.39,1539.88 v1(5299.96,1539.88) ; U102.13@5280.12,480.2 5280.12,468.39 5294.88,453.62 ; v3(5288.5,325) C112.2@5288.5,368.5 ; C112.2@5288.5,370 5288.5,413.62 5294.88,420 5294.88,453.62 ; U102.14@5305.71,480.2 5305.71,464.45 5294.88,453.62 ; C411.2@5340,1635 v1(5370,1635) ; v1(5350,1530) C410.2@5350,1565 ; C400.2@5370,1415 v1(5395,1415) ; C409.2@5430,1360 v1(5430,1390) ; R117.1@5498.5,455 C114.2@5498.5,415 v3@5523.5,390 ; C404.2@5515,1360 v1(5515,1385) ; U401.28@5519.49,1100.16 5539.84,1100.16 5550,1090 ; v1(5520.47,1430.47) U400.4@5555.32,1430.47 ; C403.2@5555,1360 v1(5555,1385) ; U101.6@5594.09,255 R121.1@5665,255 ; C402.2@5600,1585 v1(5600,1610) ; v1(5675,1540) RUSB.1@5700,1540
  Top Layer w12: U1.41@2737.01,1914.76 2737.01,1967.01 v1(2760,1990) ; C23.2@4608.62,2265 v2(4655,2265)
  Top Layer w15: v1(2885,1350) C2.1@2885,1375 ; v1(2935,1325) C7.1@2935,1355 ; S1.1@3516.93,250 v1(3555,250) ; C24.2@4640,2350 v2(4700,2350)
  Bottom Layer w10: v4(4643.09,1385) v4(4680,1385) ; 4645.99,639.01 4724.49,639.01 4748.29,615.21 v4(4759.69,615.21) ; v4(4680,1348.09) v4(4680,1385) ; v4(4680,1421.91) v4(4680,1385) ; v4(4716.91,1385) v4(4680,1385) ; v4(4796.59,541.39) v4(4833.5,541.39) ; v4(4833.5,504.49) v4(4833.5,541.39) ; v4(4833.5,578.3) v4(4833.5,541.39) ; v4(4870.41,541.39) v4(4833.5,541.39) ; v6(5275.2,555) v6(5318.5,555) ; v6(5318.5,511.69) v6(5318.5,555) ; v6(5318.5,598.31) v6(5318.5,555) ; v6(5361.81,555) v6(5318.5,555)
  other v1: 2100,750 2100,850 2200,900 2100,950 2250,1000
  other v3: 5510,145 5430,150 5305,225 4449.57,390 5530,390 5500,670
  other v4: 4759.69,467.58 4833.5,467.58 4907.32,467.58 4759.69,541.39 4907.32,541.39 4833.5,615.21 4907.32,615.21 5425,1051.93 5366.93,1110 5483.07,1110 5425,1168.07 4606.18,1311.18 4753.82,1311.18 4606.18,1385 4753.82,1385 4606.18,1458.82 4680,1458.82 4753.82,1458.82 5215.32,1575.32 5254.69,1575.32 5215.32,1614.69 5254.69,1614.69
  other v5: 4425,175 5775,175 3800,200 4000,200 4400,800 5675,950 4150,1075 4150,1225 4600,1850 200,2700 700,2700 1200,2700 4700,2900 500,3000 1000,3000 200,3300 700,3300 1200,3300 4700,3300 5675,3300 3875,3625 4250,3625 5675,3625
TARGET_VCC: J32.1 JP3.2 S5.2 | length 1090.1
  Bottom Layer w50: JP3.2@2050,650 2050,550 2300,550 J32.1@2300,650 2300,735 2399,834 2716,834 2750,800 S5.2@2750,750
TCK: R34.1 R39.2 R52.2 U1.20 | length 4238.1
  Top Layer w10: U1.20@2737.01,1385.24 2737.01,1422.01 2745,1430 2760,1430 2820,1370 2820,1260 2910,1170 v1(2910,1070) 2975,1005 v1(3065,1005) ; v1(2790,955) 2790,600 2800,590 R39.2@2800,560 ; v2(3370,1420) v2(3370,1790) ; v2(3520,1940) 3570,1990 R52.2@3570,2040.83 3539.17,2040.83 3520,2060 v2(3520,2290) ; v2(4100,2820) 4100,3240 4110,3250 R34.1@4330,3250
  Bottom Layer w10: v1(2790,955) 2790,985 2875,1070 v1(2910,1070) ; v1(3065,1005) 3065,1115 v2(3370,1420) ; v2(3370,1790) v2(3520,1940) ; v2(3520,2290) 3540,2310 3590,2310 v2(4100,2820)
TDI: R32.1 R37.2 R54.2 U1.18 | length 4796.5
  Top Layer w10: R37.2@2600,560 2600,610 2640,650 v1(2640,1005) ; U1.18@2697.64,1385.24 2697.64,1347.36 2705,1340 2770,1340 2800,1310 2800,1230 v1(2870,1160) 2870,1030 2945,955 v1(3085,955) ; v2(3209.06,1091.05) 3209.06,1279.06 3220,1290 R54.2@3250,1290 3250,1790 3290,1830 v2(3290,2310) ; v2(4000,2820) 4000,3350 4100,3450 R32.1@4330,3450
  Bottom Layer w10: v1(2640,1005) 2740,1105 2815,1105 v1(2870,1160) ; v1(3085,955) 3170,955 3209.06,994.06 v2(3209.06,1091.05) ; v2(3290,2310) 3340,2360 3540,2360 v2(4000,2820)
TDO: R29.1 R36.2 R53.2 U1.17 | length 3796.2
  Top Layer w10: R36.2@2500,560 2500,650 2450,700 2450,940 2495,985 v1(2580,985) ; U1.17@2677.95,1385.24 2677.95,1342.05 2700,1320 2755,1320 2780,1295 2780,1195 v1(2810,1165) ; v1(2915,1270) 2916,1269 3054,1269 3090,1305 3090,1370 3110,1390 3175,1390 3190,1375 R53.2@3190,1340 3210,1340 3230,1360 3230,1840 v2(3240,1840) ; v2(4300,2780) 4300,2840 4310,2850 R29.1@4330,2850
  Bottom Layer w10: v1(2580,985) 2720,1125 2770,1125 v1(2810,1165) v1(2915,1270) ; v2(3240,1840) 3360,1840 v2(4300,2780)
TMS: R33.1 R38.2 R55.2 U1.19 | length 4913.3
  Top Layer w10: v1(2690,965) 2690,920 2670,900 2670,650 2700,620 R38.2@2700,560 ; U1.19@2717.32,1385.24 2717.32,1427.32 2736,1446 2766.63,1446 2850,1362.63 2850,1285 v1(2920,1215) 3145,990 3390,990 3409.06,1009.06 3409.06,1279.06 3420,1290 R55.2@3450,1290 3270,1470 3270,1780 3320,1830 v2(3320,2280) ; v2(4050,2820) 4050,3300 4100,3350 R33.1@4330,3350
  Bottom Layer w10: v1(2690,965) 2795,1070 2835,1070 2920,1155 v1(2920,1215) ; v2(3320,2280) 3380,2340 3570,2340 v2(4050,2820)
Tx5vEn: J10.1 R73.2 U1.5 | length 2795.3
  Top Layer w10: R73.2@577.56,1215 635,1215 675,1175 675,955 730,900 J10.1@800,900 ; U1.5@2441.73,1385.24 2441.73,1431.73 v2(2520,1510)
  Bottom Layer w10: J10.1@800,900 898,802 1272,802 1498,1028 1498,1203 1565,1270 1745,1270 1896,1421 2191,1421 2230,1460 2470,1460 v2(2520,1510)
TX_MUX: R70.1 U8.1 | length 2533.3
  Top Layer w7: U8.1@784.29,1624.41 806.46,1624.41 840.87,1590 930,1590 950,1610 v1(950,1650)
  Top Layer w10: v1(360,1310) 360,1305 390,1275 R70.1@522.44,1275 R70.1@517.44,1270
  Bottom Layer w10: v1(360,1310) 360,1910 595,2145 1052,2145 1205,1992 1205,1794.4 1153.74,1743.15 1043.15,1743.15 v1(950,1650)
TX_PWRSW: R71.1 U4.6 | length 890.7
  Top Layer w10: R71.1@522.44,1035 522.44,997.56 720,800 915,800 950,765 950,495 962.59,482.4 U4.6@1004.13,482.4
TxPwr: J10.7 R71.2 U1.4 | length 2700.7
  Top Layer w10: R71.2@577.56,1035 608,1035 623,1020 623,922 727,818 1073,818 1100,845 J10.7@1100,900 ; U1.4@2422.05,1385.24 2422.05,1452.05 v2(2480,1510)
  Bottom Layer w10: J10.7@1100,900 1150,850 1235,850 1450,1065 1450,1245 1535,1330 1730,1330 1876,1476 2178.12,1476 2210.12,1508 2335.77,1508 2381.77,1554 2435.6,1554 2479.6,1510 v2(2480,1510)
TxSel: J10.5 U1.3 | length 2010.5
  Top Layer w10: U1.3@2402.36,1385.24 2402.36,1438.48 2404.5,1440.62 2404.5,1474.5 v2(2440,1510)
  Bottom Layer w10: J10.5@1000,900 1066,834 1244,834 1466,1056 1466,1226 1550,1310 1735,1310 1879,1454 2178.75,1454 2216.75,1492 2342.4,1492 2388.4,1538 2411.6,1538 2439.6,1510 v2(2440,1510)
UART_RXD: R26.1 R41.2 R56.2 U1.26 | length 3821.5
  Top Layer w10: U1.26@2814.76,1561.42 2928.58,1561.42 2960,1530 v2(3050,1530) ; R41.2@3000,560 v2(3000,630) ; v2(3460,740) v2(3460,1170) ; v2(3550,1500) 3550,1470 3565,1455 3596.79,1455 R56.2@3600,1451.79 ; v2@3570,1273.31 3570,1421.65 3578.35,1430 3600,1430 R56.2@3600,1451.79 ; R26.1@4330,2550 4310,2550 4270,2510 4270,2120 4035,1885 3745,1885 3670,1810 3670,1495 3660,1485 3615,1485 3600,1470 R56.2@3600,1451.79
  Bottom Layer w10: v2(3000,630) 3350,630 v2(3460,740) ; v2(3050,1530) 3518.35,1530 3548.35,1500 v2(3550,1500) ; v2(3460,1170) v2(3570,1280)
UART_TXD: R27.1 R40.2 R57.2 U1.25 | length 3920.7
  Top Layer w10: U1.25@2814.76,1541.73 2918.27,1541.73 2960,1500 v2(3000,1500) ; R40.2@2900,560 2900,580 2910,590 v2(2930,590) ; v2(3600,820) R57.2@3600,1351.79 v2(3600,1400) ; v2(3719.69,1500) 3719.69,1505.66 3706.52,1518.82 3706.52,1787.04 3730,1810.52 v2(3730,1820) ; v2(4200,2140) 4200,2545 4305,2650 R27.1@4330,2650
  Bottom Layer w10: v2(2930,590) 3370,590 v2(3600,820) ; v2(3000,1500) 3500,1500 v2(3600,1400) 3619.69,1400 v2(3719.69,1500) ; v2(3730,1820) 3880,1820 v2(4200,2140)
USB_LDO: C102.1 C103.1 C104.1 C112.1 C113.1 C202.1 C203.1 C204.1 C205.1 C408.1 C409.1 C413.1 J4.3 R106.2 R108.2 R111.1 R112.1 R118.1 R200.2 R207.2 R208.2 R209.2 R404.2 R408.2 R418.2 S202.2 U100.11 U100.15 U100.40 U101.4 U102.15 U102.16 U200.11 U200.15 U200.40 U401.3 U401.6 U401.8 U401.25 U401.26 U402.1 | length 8925.2
  Top Layer w8: U200.40@4670.16,1211.77 4670.16,1178.46 4703.62,1145 4703.62,1111.38 4725,1090 v3(4760,1090) ; U100.11@4882.72,368.17 4882.72,332.28 C103.1@4895,320 ; C102.1@4961.46,320 U100.15@4961.46,368.17 ; R418.2@5275,1286.18 5312.82,1286.18 5330,1269 ; U401.8@5356.1,1204.49 5356.1,1213.9 5330,1240 5330,1269 ; v3(5375,1315) 5375,1320 C409.1@5430,1320 5430,1295 5454.53,1270.47 U401.3@5454.53,1204.49 ; U401.6@5395.47,1204.49 5395.47,1220.47 5405,1230 5405,1255 5391,1269 5330,1269 ; v3(5505,1260) R408.2@5551.38,1260
  Top Layer w10: U200.15@4552.05,1558.23 4552.05,1634.33 4550,1636.38 4630,1636.38 4630.79,1635.59 U200.11@4630.79,1558.23 ; v3(4710,800) 4770,860 v3(4830,860) 4830,825 4829.88,824.88 4829.88,765.12 4843.35,751.65 U100.40@4843.35,714.62 ; R108.2@4790,242.63 v3(4790,275) ; R209.2@4855,1845 v1(4855,1730) 4875,1730 4910,1695 4910,1675 4925,1660 S202.2@4957.32,1660 ; C103.1@4895,320 C102.1@4955,320 4961.46,320 4990.3,320 5010,300.3 v3(5010,275) ; R112.1@5110,735 R111.1@5110,775 ; R111.1@5113.62,775 5139.5,775 v3@5159.5,755 ; U102.15@5331.3,480.2 5331.3,457.95 5342.13,447.13 5342.13,420 5348.5,413.62 C112.1@5348.5,370 v3(5348.5,325) ; U102.15@5335.2,480.2 U102.16@5356.89,480.2 ; U401.26@5519.49,1060.79 U401.25@5519.49,1041.1 5545,1015.59 v3(5545,975) ; C408.1@5545,903.62 5545,1007.5 ; v3(5568.5,190) U101.4@5568.5,229.41
  Top Layer w12: R106.2@4630,235 v3(4630,275) ; U402.1@5196.61,1539.88 5196.61,1416.89 5198.5,1415 v3(5198.5,1350) 5198.5,1316.5 5228.82,1286.18 R418.2@5275,1286.18 ; v3(5250,755) 5265,770 R118.1@5293.5,770 ; R418.2@5268.25,1280.26 R418.2@5275,1280.26 ; R404.2@5370,1365 5370,1315 v3(5375,1315)
  Top Layer w15: J4.3@4050,1150 R208.2@4290,1150 R200.2@4340,1150 4370,1150 4420,1100 4600,1100 4650,1050 4750,1050 4760,1060 v3(4760,1090)
  Bottom Layer w10: v3(4710,800) 4535,800 4510,775 4510,658.46 4610,558.46 4610,295 v3(4630,275) v3(4790,275) v3(5010,275) ; v3(5160,754.5) 5249.5,754.5 v3(5250,755) ; v3(5505,1260) 5545,1220 v3(5545,975) 5545,475.86 5438.64,369.5 5393.01,369.5 v3(5348.5,325) 5348.5,221.5 5385,185 5563.5,185 v3(5568.5,190)
  Bottom Layer w12: v3(4590,1635) 4590,1700 4620,1730 v1(4855,1730) 4855,1695 4810,1650 4810,1270 4760,1220 v3(4760,1090) 4765,1085 5160,1085 ; v3(4830,860) 4885,860 4990.5,754.5 v3(5160,754.5) 5160,1085 ; v3(5505,1260) 5505,1285 5475,1315 v3(5375,1315) 5275,1315 5240,1350 v3(5198.5,1350) 5198.5,1126.5 5200,1125 5160,1085
USB_SHIELD: J12.6 J12.7 J12.8 J12.9 J12.10 J12.11 RUSB.2 | length 570
  Top Layer w10: RUSB.2@5743.05,1536.95 J12.11@5822.36,1536.95
  Top Layer w25: J12.6@5822.36,1343.05 5912.18,1343.05 ; J12.11@5822.36,1536.95 5912.18,1536.95 ; J12.7@5912.91,1284.49 J12.8@5912.91,1403.09 J12.9@5912.91,1476.91 J12.10@5912.91,1595.51
USB_VBUS: C116.1 C117.1 C118.1 C119.1 C402.1 C410.1 C411.1 J12.1 Q101.2 R110.2 R120.1 U100.53 U101.2 U200.53 U400.1 U402.5 U402.8 | length 5211.9
  Top Layer w8: U200.53@4853.23,1316.09 4888.91,1316.09 4917,1288 4972,1288 v3(5000,1260) ; C119.1@5480,255 U101.2@5542.91,255
  Top Layer w10: v1(4540,715) C117.1@4540,665 4560,665 4614.69,610.31 U100.53@4660.28,610.31 ; v3(4655,320) 4655,300 4670,285 R110.2@4670,235 ; U402.8@5196.61,1650.12 5196.61,1661.61 5210,1675 5275,1675 ; v3(5259.5,269.94) 5379.94,269.94 5405,295 v3(5453.5,295) 5453.5,286.5 5478.5,261.5 C119.1@5478.5,250 ; U402.5@5273.39,1650.12 5273.39,1673.39 5275,1675 ; C411.1@5343.62,1675 C411.1@5340,1675 5275,1675 ; v3@5411.5,1493.5 v3(5415,1490) ; Q101.2@5787.01,729.41 5730.47,729.41 5728.5,731.38 v3(5728.5,690) 5733.5,685 5733.5,646.5 5741.38,638.62 C118.1@5793.5,638.62
  Top Layer w15: C411.1@5343.62,1675 5390,1675 5411.5,1653.5 C410.1@5411.5,1565 ; v3@5411.5,1493.5 C410.1@5411.5,1565 ; J12.1@5808.19,1491.18 5600,1491.18 C402.1@5600,1545 5500,1545 5480,1565 C410.1@5411.5,1565
  Bottom Layer w8: v3(5000,1260) 5090,1350 5125,1350 5196.61,1421.61 5196.61,1461.61 5225,1490 v3(5415,1490)
  Bottom Layer w10: v1(4540,715) 4540,675 4630,585 4630,345 v3(4655,320) 5210,320 v3@5259.78,270.22 ; v3(5259.5,269.94) v3@5259.78,270.22 ; v3(5728.5,690) v3@5730,688.5 ; v3@5259.78,270.22 5264.57,275 5265,275 5260,270 v3@5259.78,270.22
  Bottom Layer w15: v3(5415,1490) 5415,1445 5610,1250 5720,1250 5795,1175 5795,960 5728.5,893.5 v3(5728.5,690) ; v3(5453.5,295) 5488.5,330 5635,330 5660,305 5700,305 5730,335 v3@5730,688.5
